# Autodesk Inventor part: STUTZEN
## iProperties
Created: 2008-04
Part Number: STUTZEN
Material: St 37.0
Document SubType Name: Modellieren
Designer: christian
Erstellungsdatum: 16.07.2002
GesGewicht: 0,0kg
Author: christian
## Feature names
1. Erhebung7
